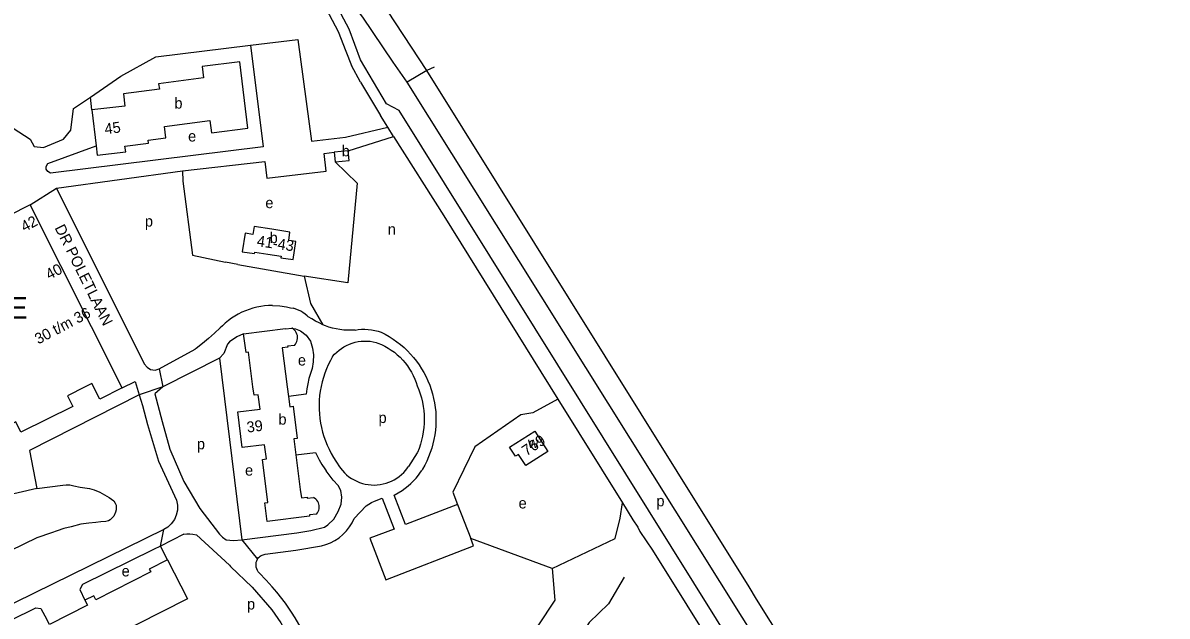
# Model space of a CAD drawing. Extents: x 158142 to 159655, y 385262 to 387204.
# Drawn here: x 159056.3 to 159478, y 386415.6 to 386634 of the extents above; entities that cross this region are included whole.
import ezdxf

# ---------------------------------------------------------------- set-up
doc = ezdxf.new("R2010")
doc.units = 0
for name, color, linetype in [('BLT_Basislijn', 7, 'Continuous'), ('BLT_Bebouwing', 7, 'Continuous'), ('BLT_Bebouwing_beschrifting', 7, 'Continuous'), ('BLT_Centroide', 7, 'Continuous'), ('BLT_Huisnummer', 7, 'Continuous'), ('BLT_Huisnummer_reeks', 7, 'Continuous'), ('BLT_Straatnaam_verkleind', 7, 'Continuous'), ('BLT_Vlakafsluiter', 7, 'Continuous')]:
    doc.layers.add(name, color=color, linetype=linetype)

msp = doc.modelspace()

# ---------------------------------------------------------------- linework, layer by layer
at = {"layer": 'BLT_Basislijn'}
for p, q in [((159180.72, 386612.1), (159177.48, 386618.34)), ((159180.72, 386612.1), (159188.13, 386599.94)), ((159081.77, 386601.93), (159081.22, 386606.67)), ((159190.81, 386595.6), (159188.13, 386599.94)), ((159192.97, 386592.1), (159190.81, 386595.6)), ((159176.24, 386586.92), (159192.97, 386592.1)), ((159167.34, 386585.87), (159171.06, 386586.34)), ((159068.74, 386573.16), (159115.12, 386579.46)), ((159135.55, 386545.04), (159130.96, 386545.83)), ((159135.55, 386545.04), (159160.04, 386540.75)), ((159128.86, 386510.55), (159107.86, 386499.93)), ((159128.86, 386510.55), (159137.03, 386443.65)), ((159253.48, 386495.5), (159277.37, 386457.29)), ((159201.69, 386475.73), (159198.44, 386470.63)), ((159216.52, 386456.68), (159221.38, 386444.11)), ((159277.37, 386457.29), (159281.12, 386450.98)), ((159109.65, 386436.3), (159107.08, 386441.36))]:
    msp.add_line(p, q, dxfattribs=at)
for points in [[(159205.26, 386616.42), (159170.82, 386668.91), (159153.76, 386696.49)], [(159478.02, 386149.53), (159467.1, 386166.67), (159451.19, 386191.65), (159448.58, 386196.2), (159403.98, 386267.32), (159376.84, 386309.95), (159320.35, 386401.06), (159194.99, 386601.74), (159190.31, 386604.18), (159180.82, 386620.38), (159176.63, 386631.64), (159172.66, 386639.08), (159146.46, 386681.4), (159151.12, 386684.55)], [(159085.3, 386660.77), (159089.06, 386662.5), (159093, 386663.81), (159098.61, 386665.26), (159107.4, 386667.76), (159111.54, 386669.09), (159115.44, 386670.99), (159121.25, 386674.65), (159124.79, 386676.76), (159128.48, 386678.59), (159132.54, 386679.78), (159138.02, 386680.36), (159138.09, 386678.86), (159140.02, 386678.97), (159142.72, 386678.38), (159144.72, 386676.48), (159169.22, 386637.05), (159172.52, 386630.87), (159175.32, 386623.61), (159177.48, 386618.34)], [(159085.3, 386660.77), (159053.17, 386640.17), (159044.04, 386630.1), (159040.22, 386623.44), (159037.96, 386617.94), (159037.14, 386612.74), (159038.41, 386607.15), (159041.39, 386602.67), (159045.98, 386599.46), (159059.02, 386591.14), (159060.49, 386588.42)], [(159197.96, 386612.2), (159192.8, 386619.56), (159181.61, 386636.06), (159176.92, 386642.07), (159170.69, 386648.92)], [(159140.28, 386625.72), (159144.86, 386588.31), (159066.49, 386578.71), (159065.49, 386579.26), (159064.97, 386580.09), (159064.98, 386581.06), (159065.56, 386582.23), (159083.32, 386588.72)], [(159081.22, 386606.67), (159092.41, 386614.32), (159105.39, 386621.45), (159140.28, 386625.72)], [(159140.28, 386625.72), (159157.62, 386627.85), (159162.66, 386590.49)], [(159413.02, 386283.52), (159409.77, 386288.65), (159364.7, 386361.34), (159326.64, 386421.78), (159323.99, 386426.39), (159205.26, 386616.42)], [(159406.2, 386279.27), (159382.73, 386316.66), (159365.07, 386339.65), (159364.85, 386340.38), (159339.3, 386382.12), (159329.59, 386402.01), (159197.96, 386612.2)], [(159060.49, 386588.42), (159063.96, 386588.14), (159071.33, 386591.13), (159073.99, 386594.46), (159075, 386602.42), (159081.22, 386606.67)], [(159162.66, 386590.49), (159175.18, 386591.91), (159175.18, 386591.91), (159190.81, 386595.6)], [(159192.97, 386592.1), (159211.45, 386562.93), (159253.48, 386495.5)], [(159115.12, 386579.46), (159145.55, 386582.95), (159146.27, 386576.84), (159168.09, 386579.39), (159167.34, 386585.87)], [(159171.45, 386582.83), (159179.55, 386575), (159176.11, 386538.29), (159160.04, 386540.75)], [(159115.12, 386579.46), (159115.33, 386575.67), (159118.87, 386548.43), (159130.96, 386545.83)], [(159068.74, 386573.16), (159100.99, 386508.46), (159102.13, 386507.17), (159103.4, 386506.34), (159105.07, 386506.18), (159106.59, 386506.67)], [(159160.04, 386540.75), (159162.37, 386530.68), (159166.91, 386522.87)], [(159148.35, 386529.94), (159146.89, 386529.9), (159145.43, 386529.78), (159143.99, 386529.58), (159142.55, 386529.3), (159141.14, 386528.94), (159139.74, 386528.51), (159138.37, 386528), (159137.03, 386527.42), (159135.73, 386526.76), (159134.46, 386526.03), (159133.24, 386525.24), (159132.06, 386524.38), (159130.92, 386523.45), (159129.85, 386522.47), (159129.09, 386521.71)], [(159148.35, 386529.94), (159151.08, 386529.81), (159153.51, 386529.41), (159155.02, 386529.12), (159156.12, 386528.9)], [(159161.11, 386526.11), (159160.37, 386526.75), (159159.57, 386527.33), (159158.74, 386527.84), (159157.86, 386528.27), (159156.95, 386528.64), (159156.12, 386528.9)], [(159166.91, 386522.87), (159165.51, 386523.5), (159164.14, 386524.2), (159162.82, 386524.98), (159161.53, 386525.82), (159161.11, 386526.11)], [(159178.74, 386520.9), (159177.36, 386520.82), (159175.97, 386520.82), (159174.58, 386520.9), (159173.2, 386521.05), (159171.84, 386521.29), (159170.48, 386521.61), (159169.15, 386522.01), (159167.85, 386522.48), (159166.91, 386522.87)], [(159129.09, 386521.71), (159126.96, 386519.72), (159124.77, 386517.79), (159122.54, 386515.92), (159120.25, 386514.11), (159119.85, 386513.81)], [(159137.7, 386519.52), (159135.14, 386518.41), (159132.43, 386516.58), (159131.76, 386515.7), (159130.45, 386512.27), (159128.86, 386510.55)], [(159155.5, 386521.58), (159156.82, 386521.36), (159158.71, 386520.65), (159160.75, 386519.06), (159162.37, 386516.75), (159163.13, 386514.17), (159163.39, 386511.74), (159163.34, 386509.14), (159162.91, 386506.73), (159162.9, 386506.7), (159162.29, 386504.87), (159161.77, 386503.01), (159161.33, 386501.13), (159160.98, 386499.23), (159160.73, 386497.31), (159154.19, 386496.48)], [(159178.74, 386520.9), (159179.96, 386521.08), (159181.18, 386521.18), (159182.41, 386521.2), (159183.63, 386521.14), (159184.85, 386521), (159186.06, 386520.78), (159187.25, 386520.48), (159188.41, 386520.11)], [(159188.41, 386520.11), (159189.91, 386519.34), (159191.38, 386518.49), (159192.8, 386517.58), (159194.18, 386516.6), (159195.52, 386515.56), (159196.8, 386514.45), (159198.03, 386513.29), (159199.2, 386512.07), (159200.31, 386510.79), (159201.36, 386509.47), (159202.35, 386508.09), (159203.27, 386506.67), (159204.12, 386505.21), (159204.91, 386503.71), (159205.62, 386502.18), (159206.26, 386500.61), (159206.82, 386499.01), (159207.31, 386497.39), (159207.72, 386495.75), (159208.05, 386494.09), (159208.3, 386492.42), (159208.48, 386490.74), (159208.57, 386489.05), (159208.58, 386487.36), (159208.52, 386485.66), (159208.37, 386483.98), (159208.15, 386482.3), (159207.84, 386480.64), (159207.46, 386478.99), (159207, 386477.36), (159206.46, 386475.76), (159205.85, 386474.18), (159205.17, 386472.63), (159204.41, 386471.12), (159203.58, 386469.64), (159203.34, 386469.24)], [(159170.49, 386511.14), (159171.22, 386511.98), (159172.01, 386512.76), (159172.85, 386513.48), (159173.74, 386514.14), (159174.68, 386514.74), (159175.66, 386515.26), (159176.67, 386515.72), (159177.71, 386516.1), (159178.78, 386516.4), (159179.87, 386516.63), (159180.97, 386516.78), (159182.08, 386516.85), (159183.19, 386516.83), (159184.3, 386516.74), (159185.39, 386516.57), (159186.48, 386516.32), (159187.18, 386516.11)], [(159187.18, 386516.11), (159188.47, 386515.57), (159189.72, 386514.95), (159190.93, 386514.26), (159192.11, 386513.51), (159193.24, 386512.69), (159194.32, 386511.8), (159195.34, 386510.86), (159196.31, 386509.85), (159197.22, 386508.8), (159198.07, 386507.69), (159198.86, 386506.54), (159199.57, 386505.34), (159200.22, 386504.1), (159200.8, 386502.83), (159201.3, 386501.53), (159201.69, 386500.33)], [(159106.59, 386506.67), (159119.85, 386513.81)], [(159170.49, 386511.14), (159169.66, 386509.66), (159168.9, 386508.14), (159168.22, 386506.59), (159167.61, 386505.01), (159167.07, 386503.4), (159166.61, 386501.77), (159166.23, 386500.12), (159165.93, 386498.45), (159165.7, 386496.77), (159165.56, 386495.08), (159165.49, 386493.38), (159165.5, 386491.69), (159165.6, 386489.99), (159165.77, 386488.31), (159166.03, 386486.63), (159166.36, 386484.97), (159166.77, 386483.32), (159167.26, 386481.7), (159167.82, 386480.1), (159168.46, 386478.53), (159169.17, 386476.99), (159169.96, 386475.49), (159170.81, 386474.02), (159171.73, 386472.6), (159172.22, 386471.9)], [(159092.88, 386499.58), (159097.68, 386502.01), (159099.23, 386497.06)], [(159107.86, 386499.93), (159104.96, 386497.39), (159107.65, 386487.28), (159110.54, 386477.03), (159115.61, 386465.17), (159121.58, 386455.16), (159128.77, 386445.7), (159129.95, 386444.58), (159131.31, 386443.69), (159134.02, 386443.47), (159137.03, 386443.65)], [(159201.69, 386500.33), (159202.28, 386498.87), (159202.79, 386497.39), (159203.23, 386495.88), (159203.59, 386494.35), (159203.87, 386492.8), (159204.07, 386491.24), (159204.2, 386489.68), (159204.24, 386488.11), (159204.2, 386486.53), (159204.09, 386484.97), (159203.89, 386483.41), (159203.62, 386481.86), (159203.26, 386480.33), (159202.83, 386478.82), (159202.33, 386477.33), (159201.74, 386475.87), (159201.69, 386475.73)], [(159099.23, 386497.06), (159058.76, 386476.6), (159061.51, 386462.57)], [(159099.23, 386497.06), (159100.48, 386493.09), (159102.29, 386486.08), (159106.32, 386472.61), (159112.2, 386459.84), (159112.9, 386458.25), (159113.29, 386456.48), (159113.29, 386454.62), (159112.89, 386452.79), (159112.18, 386451.12), (159111.04, 386449.5), (159109.72, 386448.27), (159108.26, 386447.42)], [(159253.48, 386495.5), (159244.27, 386490.47), (159239.81, 386489.62), (159222.91, 386477.91), (159214.79, 386461.17), (159216.52, 386456.68)], [(159156.97, 386474.95), (159164.18, 386475.86), (159164.68, 386474.78), (159165.58, 386473.07), (159166.55, 386471.4), (159167.58, 386469.81), (159168.12, 386469.04)], [(159137.03, 386443.65), (159157.35, 386446.18), (159162.52, 386447.04), (159167.49, 386448.3), (159168.7, 386449.16), (159170.89, 386451.31), (159172.57, 386454.06), (159173.6, 386456.75), (159173.93, 386459.42), (159173.46, 386461.78), (159172.48, 386463.63), (159170.72, 386465.6), (159168.12, 386469.04)], [(159172.22, 386471.9), (159172.77, 386470.95), (159173.4, 386470.04), (159174.09, 386469.17), (159174.84, 386468.36), (159175.65, 386467.6), (159176.51, 386466.91), (159177.42, 386466.27), (159178.37, 386465.71), (159179.36, 386465.21), (159180.39, 386464.79), (159181.44, 386464.45), (159182.51, 386464.18), (159183.6, 386463.98), (159184.7, 386463.87), (159185.81, 386463.84), (159186.92, 386463.88), (159188.02, 386464.01), (159189.1, 386464.22), (159190.17, 386464.5), (159191.22, 386464.86), (159192.24, 386465.3), (159193.22, 386465.8), (159194.17, 386466.38), (159195.07, 386467.02), (159195.92, 386467.73), (159196.72, 386468.5), (159197.46, 386469.32), (159198.14, 386470.19), (159198.44, 386470.63)], [(159216.52, 386456.68), (159197.4, 386449.3), (159193.18, 386460.12), (159196.12, 386461.88), (159197.24, 386462.65), (159198.32, 386463.49), (159199.34, 386464.38), (159200.32, 386465.34), (159201.23, 386466.35), (159202.09, 386467.41), (159202.88, 386468.52), (159203.34, 386469.24)], [(159061.51, 386462.57), (159071.05, 386463.83), (159072.25, 386463.93), (159073.66, 386463.93), (159075.12, 386463.53), (159077.41, 386463.09), (159080.84, 386462.57), (159082.57, 386462.04), (159084.65, 386461.15), (159086.41, 386460.19), (159088.2, 386459.22), (159089.9, 386457.99), (159090.38, 386457.11), (159090.66, 386456.39), (159090.76, 386455.47), (159090.7, 386454.74), (159090.47, 386453.79), (159089.91, 386452.41), (159089.48, 386452.01), (159088.94, 386451.47), (159088.5, 386451), (159087.9, 386450.62), (159086.96, 386450.42), (159085.1, 386450.26), (159083.27, 386450.05), (159080.59, 386449.84), (159077.68, 386449.38), (159074.09, 386448.48), (159071.49, 386447.86), (159068.93, 386446.96), (159066.9, 386446.19), (159061.51, 386444.44), (159046.5, 386437.11)], [(159061.51, 386462.57), (159040.75, 386457.72), (159040.28, 386451.19), (159022.7, 386446.02)], [(159166.34, 386441.4), (159168.04, 386441.88), (159169.72, 386442.56), (159171.34, 386443.41), (159172.87, 386444.44), (159174.28, 386445.63), (159175.57, 386446.96), (159176.69, 386448.4), (159177.64, 386449.93), (159178.42, 386451.52), (159182.8, 386456.2)], [(159182.8, 386456.2), (159183.8, 386456.83), (159184.83, 386457.39), (159185.9, 386457.88), (159188.71, 386458.94), (159193.11, 386447.64), (159184.24, 386444.22), (159190.15, 386428.93), (159222.42, 386441.4), (159221.38, 386444.11)], [(159251.36, 386433.07), (159274.6, 386444.09), (159276.41, 386451.64), (159277.37, 386457.29)], [(159108.26, 386447.42), (159032.81, 386410.48), (159019.6, 386403.88), (159016.58, 386403.67), (159014.61, 386403.9)], [(159281.12, 386450.98), (159282.92, 386448.37), (159283.65, 386446.69)], [(159115.71, 386445.71), (159107.08, 386441.36)], [(159115.71, 386445.71), (159116.77, 386445.89), (159117.81, 386445.92), (159118.97, 386445.78), (159120.27, 386445.46), (159132.43, 386434.32), (159132.87, 386433.9), (159140.84, 386426.2), (159148.13, 386417.86), (159151.35, 386413.14), (159156.54, 386403.77)], [(159251.36, 386433.07), (159221.38, 386444.11)], [(159283.65, 386446.69), (159288.31, 386439.83), (159375.73, 386300.12)], [(159107.08, 386441.36), (159104.47, 386440.04), (159078.29, 386427.22), (159077.37, 386425.36), (159079.2, 386421.42)], [(159145.64, 386438.35), (159156.97, 386439.87), (159166.34, 386441.4)], [(159143.45, 386431.45), (159143.09, 386431.9), (159142.78, 386432.41), (159142.54, 386432.97), (159142.37, 386433.56), (159142.29, 386434.17), (159142.29, 386434.79), (159142.37, 386435.39), (159142.54, 386435.96), (159142.76, 386436.49)], [(159142.76, 386436.49), (159142.98, 386436.81), (159143.23, 386437.11), (159143.52, 386437.38), (159143.83, 386437.63), (159144.16, 386437.85), (159144.52, 386438.03), (159144.88, 386438.18), (159145.26, 386438.28), (159145.64, 386438.35)], [(159159.7, 386409.64), (159159.41, 386410.19), (159159.12, 386410.72), (159158.09, 386412.56), (159156.72, 386414.9), (159155.38, 386417.04), (159153.14, 386420.28), (159149.94, 386424.39), (159148.22, 386426.41), (159146.03, 386428.81), (159143.45, 386431.45)], [(159251.36, 386433.07), (159252.44, 386421.45), (159240.13, 386402.93), (159227.95, 386397.14)], [(159277.97, 386429.97), (159272.13, 386420.08), (159264.98, 386413.18), (159243.67, 386379.17)], [(159023.64, 386400.21), (159061.09, 386418.61), (159063, 386418.33), (159065.21, 386414.36)]]:
    msp.add_lwpolyline(points, dxfattribs=at)
at = {"layer": 'BLT_Bebouwing'}
for p, q in [((159176.24, 386586.92), (159171.06, 386586.34)), ((159059.03, 386566.97), (159051.01, 386562.95)), ((159092.88, 386499.58), (159059.03, 386566.97))]:
    msp.add_line(p, q, dxfattribs=at)
for points in [[(159083.32, 386588.72), (159083.72, 386585.27), (159094.23, 386586.5), (159093.96, 386588.58), (159102.69, 386589.71), (159102.55, 386590.83), (159109.06, 386591.68), (159108.52, 386595.89), (159125.29, 386598.06), (159125.84, 386593.54), (159139.27, 386595.21), (159136.34, 386619.6), (159122.39, 386617.92), (159122.93, 386613.74), (159106.38, 386611.59), (159106.64, 386609.58), (159093.42, 386607.87), (159093.96, 386603.38), (159081.77, 386601.93)], [(159081.77, 386601.93), (159083.32, 386588.72)], [(159171.06, 386586.34), (159171.45, 386582.83)], [(159171.45, 386582.83), (159176.62, 386583.37), (159176.24, 386586.92)], [(159148.08, 386558.01), (159141.57, 386559), (159141.13, 386556.11), (159138.23, 386556.55), (159137.19, 386549.73), (159141.73, 386549.04), (159141.81, 386549.55), (159146.67, 386548.81)], [(159155.97, 386546.81), (159156.99, 386553.48), (159154.3, 386553.89), (159154.77, 386556.99), (159148.08, 386558.01)], [(159146.67, 386548.81), (159151.53, 386548.07), (159151.44, 386547.5), (159155.97, 386546.81)], [(159137.7, 386519.52), (159153.08, 386521.47), (159153.11, 386521.28), (159155.5, 386521.58)], [(159141.14, 386500), (159139.52, 386512.71), (159138.58, 386512.59), (159137.7, 386519.52)], [(159156.38, 386515.26), (159156.76, 386515.69), (159157.06, 386516.16), (159157.3, 386516.67), (159157.47, 386517.21), (159157.55, 386517.77), (159157.56, 386518.33), (159157.49, 386518.89), (159157.33, 386519.43), (159157.11, 386519.95), (159156.81, 386520.43), (159156.45, 386520.86), (159156.03, 386521.24), (159155.56, 386521.55), (159155.5, 386521.58)], [(159156.38, 386515.26), (159153.92, 386514.96), (159153.96, 386514.58), (159151.92, 386514.32), (159153.74, 386500), (159154.19, 386496.48)], [(159079.28, 386500), (159072.77, 386496.72), (159074.74, 386492.79), (159055.65, 386483.24), (159053.69, 386487.05), (159039.81, 386480.05)], [(159081.74, 386501.24), (159079.28, 386500)], [(159092.88, 386499.58), (159084.68, 386495.44), (159081.74, 386501.24)], [(159143.74, 386491.82), (159143.04, 386497.09), (159141.53, 386496.9), (159141.14, 386500)], [(159154.19, 386496.48), (159154.68, 386492.67), (159155.92, 386492.83), (159157.42, 386480.99), (159156.22, 386480.84), (159156.97, 386474.95)], [(159145.42, 386478.66), (159137.19, 386477.61), (159135.51, 386490.77), (159143.74, 386491.82)], [(159245.05, 386483.72), (159249.78, 386476.2), (159241.64, 386471.08), (159238.95, 386475.09), (159237.93, 386474.4), (159235.65, 386477.8), (159245.05, 386483.72)], [(159164.51, 386453.16), (159161.94, 386452.84), (159161.99, 386452.41), (159146.41, 386450.43), (159145.54, 386457.28), (159146.66, 386457.42), (159144.64, 386473.29), (159146.15, 386473.48), (159145.42, 386478.66)], [(159156.97, 386474.95), (159158.59, 386462.24)], [(159158.59, 386462.24), (159158.99, 386459.1), (159161.05, 386459.36), (159161.1, 386458.96), (159163.46, 386459.26)], [(159164.51, 386453.16), (159164.86, 386453.6), (159165.14, 386454.07), (159165.36, 386454.59), (159165.49, 386455.13), (159165.55, 386455.68), (159165.53, 386456.24), (159165.43, 386456.78), (159165.26, 386457.31), (159165.01, 386457.81), (159164.69, 386458.27), (159164.31, 386458.67), (159163.87, 386459.02), (159163.46, 386459.26)], [(159109.65, 386436.3), (159116.99, 386421.94), (159042.48, 386384.25), (159035.14, 386398.75)], [(159109.65, 386436.3), (159102.91, 386432.89), (159103.45, 386431.83), (159083.18, 386421.62), (159082.45, 386423.06), (159079.2, 386421.42)], [(159079.2, 386421.42), (159080.11, 386419.58), (159066.14, 386412.52), (159065.21, 386414.36)]]:
    msp.add_lwpolyline(points, dxfattribs=at)
at = {"layer": 'BLT_Vlakafsluiter'}
for p, q in [((159205.26, 386616.42), (159197.96, 386612.2)), ((159207.93, 386617.65), (159205.26, 386616.42)), ((159059.03, 386566.97), (159068.74, 386573.16)), ((159106.59, 386506.67), (159107.86, 386499.93)), ((159107.86, 386499.93), (159099.23, 386497.06)), ((159107.08, 386441.36), (159108.26, 386447.42)), ((159137.03, 386443.65), (159142.76, 386436.49))]:
    msp.add_line(p, q, dxfattribs=at)

# ---------------------------------------------------------------- texts
at = {"layer": 'BLT_Bebouwing_beschrifting'}
msp.add_text('GGzE', height=8, dxfattribs=at).set_placement((159029, 386525.1))
at = {"layer": 'BLT_Centroide'}
for s, p in [('b', (159112.19, 386602.44)), ('e', (159117.23, 386590.3)), ('b', (159173.84, 386584.88)), ('e', (159145.7, 386565.76)), ('p', (159101.31, 386558.98)), ('b', (159147.29, 386552.91)), ('n', (159190.82, 386556.02)), ('e', (159157.69, 386507.84)), ('b', (159150.53, 386486.06)), ('p', (159187.41, 386486.66)), ('p', (159120.48, 386476.98)), ('w', (159242.48, 386477.41)), ('e', (159138.22, 386467.3)), ('e', (159239.02, 386455.2)), ('p', (159289.82, 386456.01)), ('e', (159092.75, 386430.19)), ('p', (159138.95, 386418.01))]:
    msp.add_text(s, height=4, dxfattribs=at).set_placement(p)
at = {"layer": 'BLT_Huisnummer'}
for s, rotation, p in [('45', 7.2535, (159086.68, 386592.94)), ('39', 7.2535, (159139.08, 386483.11)), ('769', 33.8032, (159241.94, 386474.34))]:
    msp.add_text(s, height=4, rotation=rotation, dxfattribs=at).set_placement(p)
at = {"layer": 'BLT_Huisnummer_reeks'}
for s, rotation, p in [('42', 27.8253, (159056.91, 386556.92)), ('41-43', 351.8252, (159142.37, 386551.82)), ('40', 27.8253, (159066.04, 386539.29)), ('30 t/m 36', 27.8253, (159062.02, 386515.54))]:
    msp.add_text(s, height=4, rotation=rotation, dxfattribs=at).set_placement(p)
at = {"layer": 'BLT_Straatnaam_verkleind'}
msp.add_text('DR POLETLAAN', height=4, rotation=296.407, dxfattribs=at).set_placement((159067.97, 386558.53))

doc.saveas('drawing.dxf')
